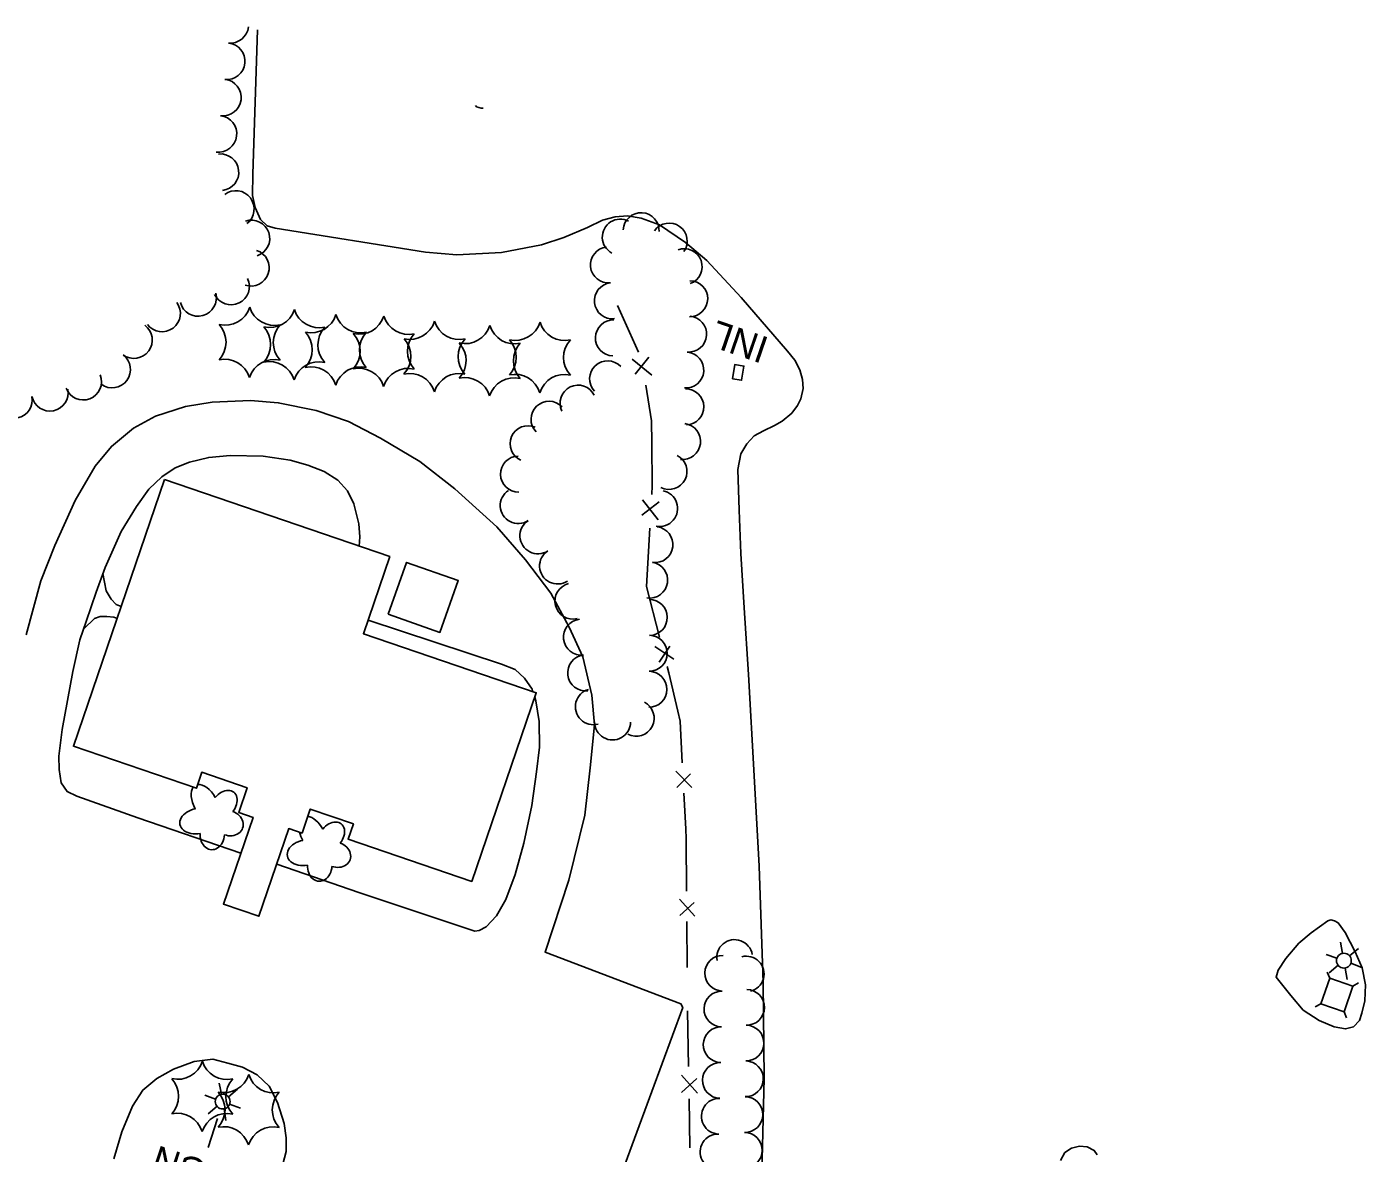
# Model space of a CAD drawing. Extents: x 189384 to 193282, y 256970 to 260388.
# Drawn here: x 191805.5 to 192101.8, y 258853.2 to 259102.3 of the extents above; entities that cross this region are included whole.
import ezdxf

# ---------------------------------------------------------------- set-up
doc = ezdxf.new("R2010")
doc.units = 0
for name, color, linetype in [('E_DWY', 7, 'Continuous'), ('E_LAND_Vegetation', 7, 'Continuous'), ('E_MISCPROP', 7, 'Continuous'), ('E_MISCPROP_HvyLine', 7, 'Continuous'), ('E_MISCPROP_Railing', 7, 'Continuous'), ('E_PATH_Sidewalk', 7, 'Continuous'), ('E_UTL_AboveGroundPipe', 7, 'Continuous')]:
    doc.layers.add(name, color=color, linetype=linetype)

# ---------------------------------------------------------------- blocks, each defined once
blk = doc.blocks.new('PED')
at = {"layer": 'E_UTL_AboveGroundPipe'}
for p, q in [((-2.34, 2.71), (-3.29, 3.77)), ((3.06, 2.71), (4.02, 3.77)), ((-3.29, -4.35), (-2.34, -3.29)), ((4.02, -4.35), (3.06, -3.29))]:
    blk.add_line(p, q, dxfattribs=at)
blk.add_lwpolyline([(-2.34, -3.29), (3.06, -3.29), (3.06, 2.71), (-2.34, 2.71)], close=True, dxfattribs=at)
blk = doc.blocks.new('INL')
at = {"layer": 'E_MISCPROP_Railing'}
blk.add_text('INL', height=6, rotation=0, dxfattribs=at).set_placement((-5.79, -2.75))
blk = doc.blocks.new('LTP_1')
at = {"layer": 'E_MISCPROP'}
for p, q in [((-0.78, 1.46), (-1.98, 3.76)), ((0.86, 1.37), (2.22, 3.6)), ((-1.61, 0.09), (-4.22, 0.17)), ((1.66, 0), (4.18, -0.07)), ((-0.86, -1.4), (-2.22, -3.59)), ((0.78, -1.44), (2.02, -3.62))]:
    blk.add_line(p, q, dxfattribs=at)
blk.add_circle((0.02, 0.01), 1.64, dxfattribs=at)
blk = doc.blocks.new('SIGN')
at = {"layer": 'E_MISCPROP'}
blk.add_text('SIGN', height=6, rotation=0, dxfattribs=at).set_placement((0, -3))
blk = doc.blocks.new('PINEL')
at = {"layer": 'E_LAND_Vegetation'}
for centre, start, end in [((-8.23, 7.26), 275.2112, 0.9761), ((2.17, 10.66), 215.2112, 300.9761), ((10.31, 3.35), 155.2112, 240.9761), ((-10.49, -3.45), 335.2112, 60.9761), ((8.05, -7.36), 95.2112, 180.9761), ((-2.35, -10.75), 35.2112, 120.9761)]:
    blk.add_arc(centre, 5.72, start, end, dxfattribs=at)

msp = doc.modelspace()

# ---------------------------------------------------------------- linework, layer by layer
at = {"layer": 'E_DWY'}
for points in [[(191856.46, 259101.57), (191855.44, 259069.68), (191855.37, 259064.95), (191855.98, 259062.28), (191857.13, 259059.64), (191858.63, 259058.27), (191860.35, 259057.74), (191893.63, 259052.42), (191900.56, 259051.84), (191910.4, 259052.37), (191919.3, 259054.04), (191924.19, 259055.66), (191929.42, 259057.9), (191932.79, 259059.48), (191935.56, 259060.2), (191938.31, 259060.43), (191941.27, 259059.97), (191945.33, 259058.45), (191951.07, 259054.59), (191955.83, 259050.56), (191963.42, 259042.43), (191973.64, 259030.56), (191975.29, 259028.55), (191976.4, 259026.4), (191976.98, 259024.26), (191977.11, 259022.26), (191976.6, 259020.01), (191975.89, 259018.49), (191974.64, 259016.84), (191972.48, 259015.02), (191970.8, 259014.09), (191968.38, 259012.9), (191966.28, 259011.79), (191964.66, 259010.06), (191963.34, 259007.85), (191962.7, 259004.39), (191962.96, 258995.35), (191963.37, 258985.77), (191964.04, 258973.77), (191965.01, 258959.01), (191966.25, 258936.63), (191967.39, 258916.68), (191968.3, 258890.96), (191968.49, 258869.76), (191967.73, 258839.81)], [(191904.64, 259084.89), (191904.91, 259084.57), (191905.96, 259084.26), (191906.38, 259084.29)], [(191805.35, 258967.79), (191808.61, 258979.78), (191811.68, 258987.54), (191816.19, 258997.51), (191820.56, 259005.12), (191824.2, 259009.46), (191829.03, 259013.52), (191833.9, 259016.13), (191840.56, 259018.32), (191846.47, 259019.29), (191854.95, 259019.61), (191861.08, 259019.13), (191869.45, 259017.39), (191876.59, 259014.98), (191883.69, 259011.29), (191892.34, 259006.11), (191900.12, 259000.11), (191909.4, 258991.69), (191915.74, 258984.37), (191921.32, 258976.99), (191925.38, 258969.52), (191928.39, 258962.98), (191930.41, 258954.5), (191930.95, 258947.91), (191930.05, 258938.41), (191928.86, 258927.9), (191925.28, 258913.55), (191920.05, 258897.62), (191950.1, 258886.21), (191950.5, 258885.42), (191943.69, 258866.81), (191930.63, 258831.49)], [(191852.81, 258919.56), (191830, 258927.37), (191816.53, 258932.13), (191814.39, 258933.17), (191813.04, 258935.06), (191812.61, 258938.04), (191812.56, 258941), (191813.26, 258946.88), (191815.62, 258959.68), (191817.18, 258966.74), (191818.62, 258970.74), (191820.82, 258977.28), (191822.77, 258982.72), (191826.35, 258990.67), (191829.7, 258996.2), (191832.42, 259000), (191835.34, 259002.78), (191838.27, 259004.71), (191841.48, 259006), (191845.69, 259007.03), (191850.46, 259007.43), (191857.71, 259007.34), (191863.69, 259006.46), (191867.62, 259005.35), (191871.25, 259003.89), (191874.24, 259002.02), (191876.41, 258999.67), (191877.77, 258996.8), (191878.86, 258992.35), (191879.14, 258989.5), (191878.96, 258987.44)], [(191880.92, 258971.08), (191910.42, 258961.35), (191913.46, 258960.14), (191915.51, 258958.25), (191917.18, 258955.82), (191917.37, 258955.24)], [(191917.78, 258954.02), (191918.05, 258953.19), (191918.73, 258948.63), (191918.82, 258942.94), (191918.19, 258937.49), (191917.12, 258930.04), (191915.36, 258921.74), (191913.46, 258914.8), (191911.37, 258909.3), (191909.3, 258905.69), (191907.06, 258903.23), (191905.52, 258902.43), (191904.54, 258902.27), (191878.87, 258910.8), (191860.73, 258917.13)], [(192084.97, 258888.05), (192087.66, 258884.84), (192091.23, 258882.56), (192094.5, 258881.12), (192097.04, 258880.68), (192098.79, 258881.14), (192100.09, 258882.53), (192100.64, 258884.17), (192101.28, 258886.9), (192101.45, 258890.39), (192100.68, 258894.2), (192099.15, 258897.7), (192096.91, 258901.99), (192095.39, 258904.1), (192094.62, 258904.57), (192093.78, 258904.78), (192093.1, 258904.56), (192089.45, 258901.93)], [(192089.45, 258901.93), (192086.73, 258899.63), (192083.83, 258896.27), (192082.13, 258893.64), (192081.67, 258892.13), (192084.97, 258888.05)], [(191861.72, 258849.39), (191862.79, 258853.56), (191862.83, 258856.61), (191862.39, 258859.75), (191860.91, 258864.4), (191859.09, 258868.03), (191856.41, 258870.55), (191853.19, 258872.22), (191849.91, 258873.12), (191846.58, 258873.95), (191842.51, 258873.45), (191837.93, 258871.75), (191834.2, 258869.69), (191831.14, 258867.14), (191828.85, 258863.6), (191826.52, 258857.93), (191824.69, 258851.95)], [(192033.98, 258851.56), (192034.96, 258853.31), (192036.41, 258854.33), (192038.23, 258854.77), (192039.92, 258854.61), (192041.49, 258853.79), (192042.15, 258852.8)]]:
    msp.add_lwpolyline(points, dxfattribs=at)
at = {"layer": 'E_LAND_Vegetation'}
for centre, radius, start, end in [((191850.46, 259102.69), 4.05, 264.2692, 353.8619), ((191849.66, 259094.63), 4.05, 264.2692, 84.2692), ((191848.83, 259086.62), 4.05, 263.0163, 83.0163), ((191847.84, 259078.58), 4.05, 263.0163, 83.0163), ((191848.29, 259070.1), 4.05, 276.2229, 96.2229), ((191851.69, 259061.97), 4.05, 307.4264, 127.4264), ((191855.14, 259055.45), 4.05, 288.526, 108.526), ((191936.69, 259055.76), 3.98, 62.4652, 242.4652), ((191941.31, 259057.16), 3.98, 357.0769, 177.0769), ((191947.51, 259054.86), 3.98, 324.6986, 144.6986), ((191934.06, 259049.6), 3.98, 96.3633, 276.3633), ((191855.01, 259048.97), 4.05, 251.5228, 71.5228), ((191950.81, 259049.21), 3.98, 289.9198, 109.9198), ((191850.65, 259044.84), 4.05, 205.5348, 25.5348), ((191934.94, 259041.68), 3.98, 96.3633, 276.3633), ((191952.03, 259042.13), 3.98, 269.3992, 89.3992), ((191843.34, 259042.32), 4.05, 195.2019, 15.2019), ((191835.38, 259038.88), 4.05, 216.8441, 36.8441), ((191829.17, 259032.99), 4.05, 233.5726, 53.5726), ((191935.16, 259033.48), 3.98, 88.2912, 268.2912), ((191951.79, 259034.3), 3.98, 265.5034, 85.5034), ((191824.35, 259026.47), 4.05, 233.5726, 53.5726), ((191951.16, 259026.36), 3.98, 265.5034, 85.5034), ((191933.88, 259024.41), 3.98, 42.9408, 222.9408), ((191817.93, 259023.79), 4.05, 201.3555, 21.3555), ((191810.58, 259021.34), 4.05, 191.4446, 11.4446), ((191927.35, 259019.04), 3.98, 26.1103, 206.1103), ((191951.19, 259018.2), 3.98, 271.5745, 91.5745), ((191802.64, 259019.74), 4.05, 191.4446, 11.4446), ((191920.94, 259015.48), 3.98, 43.9697, 223.9697), ((191916.3, 259010.07), 3.98, 66.7, 246.7), ((191950.45, 259010.56), 3.98, 263.0425, 83.0425), ((191914.19, 259003.36), 3.98, 91.2415, 271.2415), ((191947.46, 259003.94), 3.98, 243.1141, 63.1141), ((191914.13, 258996.39), 3.98, 123.0679, 303.0679), ((191945.39, 258995.76), 3.98, 259.1072, 79.1072), ((191918.48, 258989.71), 3.98, 123.0679, 303.0679), ((191944.34, 258987.75), 3.98, 262.8106, 82.8106), ((191922.83, 258983.03), 3.98, 123.0679, 303.0679), ((191943.18, 258979.91), 3.98, 261.4242, 81.4242), ((191926.21, 258975.27), 3.98, 104.0351, 284.0351), ((191943.1, 258971.65), 3.98, 270.7185, 90.7185), ((191928.1, 258967.29), 3.98, 96.7042, 276.7042), ((191943.1, 258963.73), 3.98, 269.3827, 89.3827), ((191929.03, 258959.38), 3.98, 96.7042, 276.7042), ((191943.02, 258955.76), 3.98, 269.3827, 89.3827), ((191930.74, 258951.91), 3.98, 105.5556, 285.5556), ((191940.19, 258949.38), 3.98, 242.4351, 62.4351), ((191934.98, 258948.54), 3.98, 179.9175, 359.9175), ((191961.97, 258896.46), 3.95, 10.0817, 190.0817), ((191959.32, 258892.98), 3.95, 88.7611, 268.7611), ((191964.51, 258892.81), 3.95, 284.3519, 104.3519), ((191959.15, 258885.08), 3.95, 88.7611, 268.7611), ((191964.62, 258885.43), 3.95, 269.0836, 89.0836), ((191964.49, 258877.54), 3.95, 269.0836, 89.0836), ((191958.98, 258877.19), 3.95, 88.7611, 268.7611), ((191958.8, 258869.29), 3.95, 88.7611, 268.7611), ((191964.36, 258869.64), 3.95, 269.0836, 89.0836), ((191958.58, 258861.37), 3.95, 87.9929, 267.9929), ((191964.24, 258861.74), 3.95, 269.0836, 89.0836), ((191964.11, 258853.85), 3.95, 269.0836, 89.0836), ((191958.3, 258853.48), 3.95, 87.9929, 267.9929)]:
    msp.add_arc(centre, radius, start, end, dxfattribs=at)
for centre, major_axis, ratio, start_param, end_param in [((191844.94, 258930.59), (2.22, -3.95), 0.560249, 1.570796, 2.926744), ((191844.94, 258930.59), (2.22, -3.95), 0.560249, 3.38381, 4.712389), ((191849.09, 258930.3), (-2.16, -2.7), 0.716896, 1.570796, 4.712389), ((191843.27, 258926.62), (3.95, 0.75), 0.691916, 1.570796, 4.712389), ((191850.1, 258926.18), (-3.1, 1.11), 0.832022, 1.570796, 4.712389), ((191868.7, 258923.6), (2.22, -3.95), 0.560249, 1.570796, 2.706997), ((191872.84, 258923.31), (-2.16, -2.7), 0.716896, 1.570796, 4.712389), ((191846.48, 258923.74), (0.18, 3.44), 0.782863, 1.570796, 4.712389), ((191868.7, 258923.6), (2.22, -3.95), 0.560249, 4.273109, 4.712389), ((191867.03, 258919.63), (3.95, 0.75), 0.691916, 1.570796, 4.712389), ((191873.85, 258919.19), (-3.1, 1.11), 0.832022, 1.570796, 4.712389), ((191870.24, 258916.75), (0.18, 3.44), 0.782863, 1.570796, 4.712389)]:
    msp.add_ellipse(centre, major_axis=major_axis, ratio=ratio, start_param=start_param, end_param=end_param, dxfattribs=at)
at = {"layer": 'E_MISCPROP'}
msp.add_line((191845.57, 258854.45), (191847.65, 258860.84), dxfattribs=at)
at = {"layer": 'E_MISCPROP_HvyLine'}
for points in [[(191835.91, 259002.14), (191885.72, 258985.13), (191885.72, 258985.13), (191885.72, 258985.13), (191879.88, 258968.04), (191918.11, 258954.99), (191918.11, 258954.99), (191918.11, 258954.99), (191903.86, 258913.27), (191903.86, 258913.27), (191876.51, 258922.61), (191877.67, 258926.01), (191877.67, 258926.01), (191868.15, 258929.27), (191868.15, 258929.27), (191866.34, 258923.96), (191866.34, 258923.96), (191863.4, 258924.96), (191863.4, 258924.96), (191856.79, 258905.58), (191856.79, 258905.58), (191848.96, 258908.26), (191855.5, 258927.42), (191855.5, 258927.42), (191855.5, 258927.42), (191852.32, 258928.51), (191854.19, 258933.98), (191854.19, 258933.98), (191854.19, 258933.98), (191844.17, 258937.41), (191842.97, 258933.89), (191815.77, 258943.17), (191815.77, 258943.17), (191835.91, 259002.14)], [(191885.39, 258972.38), (191896.8, 258968.34), (191896.8, 258968.34), (191900.85, 258979.81), (191900.85, 258979.81), (191889.44, 258983.84), (191889.44, 258983.84), (191889.44, 258983.84)]]:
    msp.add_lwpolyline(points, close=True, dxfattribs=at)
at = {"layer": 'E_MISCPROP_Railing'}
for p, q in [((191939.34, 259028.78), (191943.67, 259025.2)), ((191943.02, 259029.19), (191939.97, 259025.46)), ((191945.27, 258997.25), (191941.48, 258994.28)), ((191941.6, 258997.66), (191945.04, 258993.22)), ((191948.5, 258962.43), (191944.35, 258965.26)), ((191945.26, 258961.77), (191947.67, 258965.34)), ((191952.47, 258934.08), (191948.97, 258937.68)), ((191949.17, 258934.07), (191952.24, 258937.09)), ((191953.14, 258905.62), (191949.81, 258909.38)), ((191949.84, 258905.77), (191953.05, 258908.65)), ((191953.77, 258866.5), (191950.19, 258870.48)), ((191950.25, 258866.62), (191953.64, 258869.72))]:
    msp.add_line(p, q, dxfattribs=at)
for points in [[(191936.06, 259040.65), (191940.68, 259030.29)], [(191942.3, 259023), (191943.58, 259015.16), (191943.64, 259010.21)], [(191943.64, 259010.21), (191943.76, 259000.72), (191943.65, 258998.86)], [(191943.22, 258991.38), (191942.49, 258978.49)], [(191945.39, 258967.33), (191942.49, 258978.49)], [(191949.38, 258950.96), (191947.45, 258959.39), (191947.08, 258960.84)], [(191950.4, 258939.5), (191949.89, 258948.74), (191949.38, 258950.96)], [(191951.23, 258922.67), (191951.21, 258924.88), (191950.77, 258932.8)], [(191951.32, 258911.13), (191951.23, 258922.67)], [(191951.46, 258894.28), (191951.38, 258904.43)], [(191951.78, 258872.36), (191951.57, 258884.65)], [(191952.09, 258854.4), (191951.91, 258865.21)]]:
    msp.add_lwpolyline(points, dxfattribs=at)
msp.add_lwpolyline([(191961.47, 259024.43), (191961.99, 259027.58), (191964.02, 259027.25), (191963.5, 259024.1)], close=True, dxfattribs=at)
at = {"layer": 'E_PATH_Sidewalk'}
for points in [[(191822.29, 258981.38), (191822.99, 258977.54), (191824.15, 258975.69), (191825.21, 258974.53), (191826.34, 258974.11)], [(191818.05, 258969.16), (191820.47, 258971.45), (191821.72, 258971.86), (191823.18, 258971.86), (191824.69, 258971.68), (191825.43, 258971.45)]]:
    msp.add_lwpolyline(points, dxfattribs=at)

# ---------------------------------------------------------------- block references
at = {"layer": 'E_LAND_Vegetation'}
for p, rotation in [((191854.64, 259032.47), 161.72867557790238), ((191864.51, 259031.95), 161.72867540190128), ((191873.7, 259030.81), 161.72867523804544), ((191884.29, 259030.49), 161.72867504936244), ((191895.51, 259029.34), 161.7286748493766), ((191918.82, 259029.13), 161.7286744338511), ((191907.72, 259028.4), 161.72867463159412), ((191844.17, 258865.73), 161.72867575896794), ((191854.42, 258862.78), 161.72867557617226)]:
    msp.add_blockref('PINEL', p, dxfattribs=dict(at, rotation=rotation))
at = {"layer": 'E_MISCPROP'}
for name, p, rotation in [('LTP_1', (192096.68, 258895.77), 161.72867125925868), ('LTP_1', (191848.8, 258864.62), 161.7286756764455), ('SIGN', (191852.15, 258845.99), 161.7286756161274)]:
    msp.add_blockref(name, p, dxfattribs=dict(at, rotation=rotation))
at = {"layer": 'E_MISCPROP_Railing', "rotation": 161.06331572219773}
msp.add_blockref('INL', (191963.49, 259032.68), dxfattribs=at)
at = {"layer": 'E_UTL_AboveGroundPipe', "rotation": 161.06331336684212}
msp.add_blockref('PED', (192095.37, 258887.78), dxfattribs=at)

doc.saveas('drawing.dxf')
